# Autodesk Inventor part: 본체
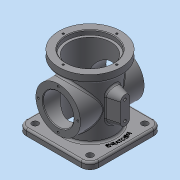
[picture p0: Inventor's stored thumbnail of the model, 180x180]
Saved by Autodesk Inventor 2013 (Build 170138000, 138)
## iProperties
Created: 2021-03
Part Number: 본체
Material: Generic
Document SubType Name: Modeling
Designer: Administrator
Density: 1 g/cm^3
Author: Administrator
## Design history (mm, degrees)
sketch "스케치1"
  geometry: L1 (-57, -57)-(57, -57); L2 (57, -57)-(57, 57); L3 (57, 57)-(-57, 57); L4 (-57, 57)-(-57, -57); L5 (-57, -57)-(57, 57); L6 (57, -57)-(-57, 57); 1 further point
  constraints: 12 end point, 2 midpoint, 2 parallel, 2 perpendicular, 1 horizontal
  dimensions: "d0" = 114 distance of L2.end L3.end
extrude "돌출1" new body sketch "스케치1" distance "d2" = 10; taper "d3" = 0 deg
sketch "스케치3"
  geometry: C1 r 38 at (0, 0); 1 further point
  constraints: 1 centre point, 1 coincident
  dimensions: "d4" = 76 diameter of C1
extrude "돌출2" join sketch "스케치3" distance "d6" = 88; taper "d7" = 0 deg
sketch "스케치4"
  geometry: C1 r 49 at (0, 0); 1 further point
  constraints: 1 centre point, 1 coincident
  dimensions: "d8" = 98 diameter of C1
extrude "돌출3" join sketch "스케치4" distance "d10" = 13; taper "d11" = 0 deg
sketch "스케치5"
  geometry: L1 (57, 0)-(-57, 0) reference; C1 r 35 at (0, 54); 1 further point
  constraints: 1 centre point, 1 vertical alignment
  dimensions: "d12" = 70 diameter of C1; "d14" = 54 distance from line of L1 C1.centre
extrude "돌출4" join sketch "스케치5" stored distance "d15" = 100; taper "d16" = 0 deg
hole "구멍1" diameter "d19" = 66; stored, may be unused: countersink angle "d23" = 90 deg, drill point angle "d25" = 118 deg; dims "d17" = 10, "d18" = 10, "d20" = 6, "d21" = 74, "d22" = 7, "d24" = 8
hole "구멍2" diameter "d28" = 48; stored, may be unused: countersink angle "d32" = 90 deg, drill point angle "d34" = 118 deg; dims "d26" = 10, "d27" = 10, "d29" = 6, "d30" = 74, "d31" = 7, "d33" = 8
chamfer "모따기1" distance "d35" = 1; stored, may be unused: second distance "d36" = 2, angle "d37" = 45 deg
chamfer "모따기2" distance "d38" = 1; stored, may be unused: second distance "d39" = 2, angle "d40" = 45 deg
fillet "모깎기1" dims "d41" = 3
fillet "모깎기2" dims "d42" = 14
fillet "모깎기3" dims "d43" = 3
node "작업 평면1"
sketch "스케치6"
  geometry: L1 (-7, 41)-(-7, 70); L2 (7, 70)-(7, 41); L3 (-43, 0)-(43, 0) reference; L4 (-80.664, 54)-(67.683, 54); A1 r 7 centre (0, 70) between (7, 70) and (-7, 70); A2 r 7 centre (0, 41) between (-7, 41) and (7, 41); 2 further points
  constraints: 6 end point, 4 point on circle, 4 tangent, 2 centre point, 1 midpoint, 1 parallel, 1 vertical, 1 vertical alignment
  dimensions: "d45" = 14 distance between parallel lines of L1 L2; "d47" = 29 distance of A1.centre A2.centre; "d90" = 54 distance between parallel lines of L3 L4; "d91" = 13 distance from line of A2.centre L4
extrude "돌출5" join sketch "스케치6" stored distance "d49" = 10; taper "d50" = 15 deg
sketch "스케치7"
  geometry: A1 r 42 centre (0, 0) between (0, 42) and (-42, 0); 3 further points
  constraints: 4 point on circle, 2 horizontal alignment, 2 vertical alignment, 1 centre point, 1 coincident
  dimensions: "d51" = 84 diameter of A1
hole "구멍3" sketch "스케치7" at (0, 42), (-42, 0), (0, -42), (42, 0) diameter "d53" = 3.242; stored, may be unused: countersink angle "d57" = 90 deg, drill point angle "d59" = 118 deg; dims "d54" = 6, "d55" = 4, "d56" = 2, "d58" = 8
sketch "스케치8"
  geometry: C1 r 25 at (0, 0) reference; A1 r 31 centre (0, 0) between (0, 31) and (-31, 0); 3 further points
  constraints: 4 point on circle, 2 horizontal alignment, 2 vertical alignment, 1 centre point, 1 coincident
  dimensions: "d60" = 62 diameter of A1
hole "구멍4" sketch "스케치8" at (0, 31), (-31, 0), (0, -31), (31, 0) diameter "d62" = 3.242; stored, may be unused: countersink angle "d66" = 90 deg, drill point angle "d68" = 118 deg; dims "d63" = 6, "d64" = 4, "d65" = 2, "d67" = 8
fillet "모깎기4" dims "d69" = 3
sketch "스케치9"
  geometry: A1 r 7 centre (-41, 0) between (-41, -7) and (-41, 7) reference; A2 r 7 centre (-70, 0) between (-70, 7) and (-70, -7) reference; 3 further points
  constraints: 2 coincident
hole "구멍5" sketch "스케치9" at (-70, 0), (-41, 0) diameter "d70" = 4.134; stored, may be unused: countersink angle "d74" = 90 deg, drill point angle "d76" = 118 deg; dims "d71" = 8, "d72" = 4, "d73" = 2, "d75" = 10
sketch "스케치10"
  geometry: C1 r 50 at (0, 0); 1 further point
  constraints: 1 centre point, 1 coincident, 1 other
  dimensions: "d79" = 100 diameter of C1
feature "엠보싱1" sketch "스케치10" dims "d0" = 114, "d81" = 0.5, "d82" = 0
sketch "스케치11"
  geometry: A1 r 14 centre (-43, 43) between (-43, 57) and (-57, 43) reference; A2 r 14 centre (43, 43) between (57, 43) and (43, 57) reference; A3 r 14 centre (43, -43) between (43, -57) and (57, -43) reference; A4 r 14 centre (-43, -43) between (-57, -43) and (-43, -57) reference; 5 further points
  constraints: 4 coincident
hole "구멍6" sketch "스케치11" at (-43, 43), (43, 43), (43, -43), (-43, -43) diameter "d83" = 10; stored, may be unused: countersink angle "d87" = 90 deg, drill point angle "d89" = 0 deg; dims "d84" = 8, "d85" = 4, "d86" = 2, "d88" = 10
node "솔리드1"
mirror "대칭1"
other parameters: "d44" = 55
